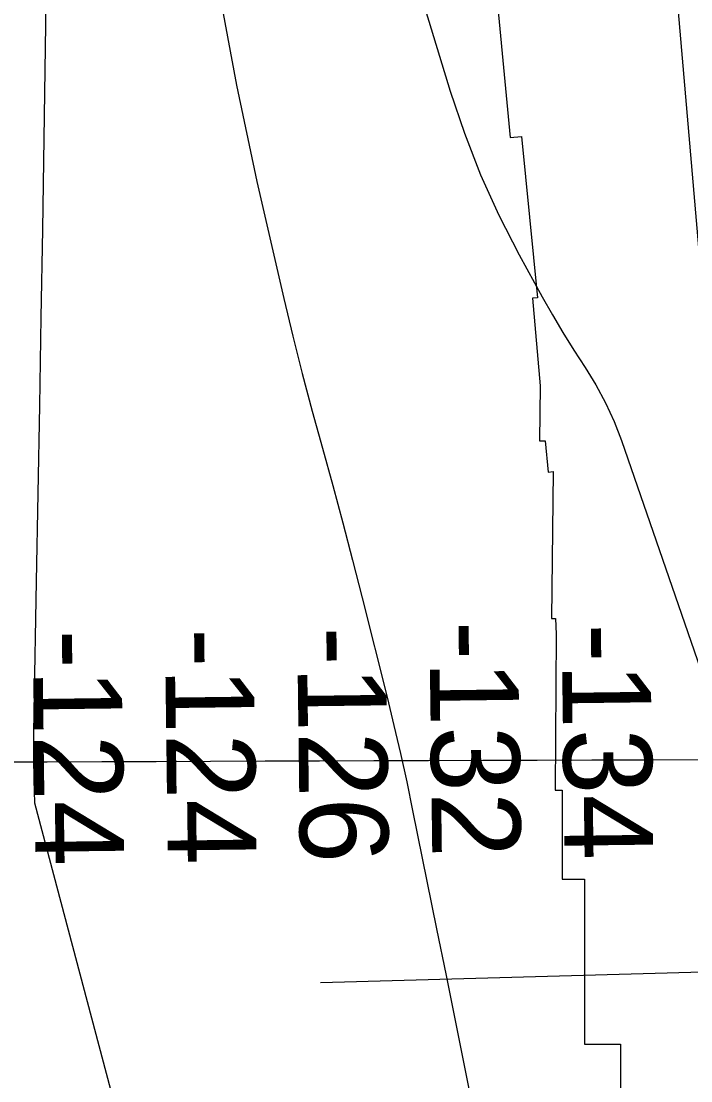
# Model space of a CAD drawing. Extents: x 3392644 to 3430565, y 576657 to 602123.
# Drawn here: x 3403450 to 3403956, y 587886 to 588688 of the extents above; entities that cross this region are included whole.
import ezdxf

# ---------------------------------------------------------------- set-up
doc = ezdxf.new("R2010")
doc.units = 0
for name, color, linetype in [('V-GRID-MAJR', 7, 'Continuous'), ('V-RIVR-RANG', 7, 'Continuous'), ('V-RRAP-RVMT', 7, 'Continuous'), ('V-TOPO-MINR', 7, 'Continuous')]:
    doc.layers.add(name, color=color, linetype=linetype)

msp = doc.modelspace()

# ---------------------------------------------------------------- linework, layer by layer
at = {"layer": 'V-GRID-MAJR'}
msp.add_spline([(3396759.069, 588105.428), (3402028.4020000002, 588122.6730000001), (3407297.732, 588140.684), (3412567.059, 588159.461), (3417836.383, 588179.004), (3423105.705, 588199.314), (3428375.023, 588220.3910000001), (3428375.024, 588220.3910000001)], degree=3, dxfattribs=at)
at = {"layer": 'V-RIVR-RANG'}
msp.add_line((3404773.4663000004, 587991.0334000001), (3403675.9011, 587960.1355), dxfattribs=at)
at = {"layer": 'V-RRAP-RVMT'}
for points in [[(3403787.4530000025, 589022.2620000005), (3403792.3760000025, 589022.6790000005), (3403803.1870000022, 588898.2240000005), (3403786.2820000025, 588896.8130000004), (3403799.6490000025, 588740.1650000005), (3403806.0080000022, 588740.6860000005), (3403819.3080000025, 588600.0000000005), (3403827.8170000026, 588600.7850000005), (3403839.9560000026, 588478.6580000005), (3403836.0480000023, 588478.3570000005), (3403842.0491820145, 588412.0041847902), (3403841.4620000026, 588370.4790000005), (3403845.8110243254, 588370.4109071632), (3403847.9510000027, 588346.7500000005), (3403851.9030192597, 588347.1069682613), (3403850.5170000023, 588235.8150000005), (3403853.604133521, 588235.7810275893), (3403853.9803775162, 588224.0148182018), (3403853.1720000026, 588106.0890000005), (3403858.7071260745, 588106.0502651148)], [(3403858.7071260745, 588106.0502651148), (3403858.6710000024, 588038.6260000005), (3403875.4310000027, 588038.7480000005), (3403875.4320000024, 587913.7160000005), (3403902.6370000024, 587913.8380000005), (3403902.6360000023, 587788.5640000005), (3403925.4690000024, 587788.5640000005), (3403925.6480000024, 587663.8410000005), (3403936.9150000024, 587663.8410000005), (3403936.9150000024, 587553.5380000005), (3403933.8540000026, 587553.5530000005), (3403934.0280000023, 587419.9890000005), (3403928.1980000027, 587310.5260000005), (3403951.0640000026, 587309.3500000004), (3403939.2910000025, 587215.2060000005), (3403940.488000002, 587215.0110000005), (3403924.5650000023, 587124.4060000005), (3403913.7950000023, 587126.3670000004), (3403888.8500000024, 586987.2380000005), (3403908.5240000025, 586983.7120000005), (3403886.9060000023, 586860.7560000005), (3403914.2310000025, 586855.8930000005), (3403892.6140000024, 586732.4500000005), (3403953.283649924, 586721.7793966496)]]:
    msp.add_lwpolyline(points, dxfattribs=at)
at = {"layer": 'V-TOPO-MINR'}
for points in [[(3403991.97834602, 588168.6326957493), (3403917.8935257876, 589028.6387163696)], [(3403471.7196410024, 588943.6111753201), (3403465.5392929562, 588530.2716853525), (3403464.497701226, 588463.7009697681), (3403463.3945110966, 588397.131317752), (3403462.198923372, 588330.5632610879), (3403460.9417372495, 588263.9962679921), (3403459.011862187, 588165.4341178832), (3403458.8154588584, 588148.1501057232), (3403458.808329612, 588130.8675702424), (3403459.0851114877, 588113.5872497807), (3403459.551167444, 588096.3084059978), (3403625.365806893, 587470.1941208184)], [(3403732.4809343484, 588770.8624191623), (3403773.8831140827, 588635.0073053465), (3403784.6929227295, 588603.1021186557), (3403796.775585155, 588571.7328043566), (3403810.767528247, 588541.1672986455), (3403826.0323251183, 588511.1376653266), (3403843.4885971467, 588479.2709980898), (3403851.1665183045, 588465.6883321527), (3403859.081644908, 588452.249673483), (3403867.3525796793, 588439.0270257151), (3403875.860719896, 588425.9483852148), (3403884.0042079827, 588412.7079417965), (3403891.4337994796, 588399.1124415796), (3403897.7925460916, 588384.9843561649), (3403903.437396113, 588370.5012139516), (3403979.915626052, 588149.3539946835)], [(3403598.661832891, 588712.8074390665), (3403612.2857686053, 588639.5211201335), (3403627.7353002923, 588566.5391246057), (3403648.193729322, 588478.0649569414), (3403654.992424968, 588449.6015972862), (3403662.0640281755, 588421.2083047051), (3403669.5449927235, 588392.9201127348), (3403677.298864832, 588364.7019878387), (3403685.126776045, 588336.5016614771), (3403692.780401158, 588308.2549747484), (3403700.1725971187, 588279.9387474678), (3403707.3905069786, 588251.5761598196), (3403726.17193478, 588176.3214248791), (3403731.343032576, 588154.9891738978), (3403736.3213192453, 588133.6133892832), (3403741.0103892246, 588112.1723042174), (3403745.506648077, 588090.6876855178), (3403763.6432930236, 588001.007506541), (3403770.7772274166, 587965.7180530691), (3403777.9074511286, 587930.4278501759), (3403785.032108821, 587895.1365231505), (3403792.1530558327, 587859.8444467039)]]:
    msp.add_lwpolyline(points, dxfattribs=at)

# ---------------------------------------------------------------- texts
at = {"layer": 'V-RIVR-RANG'}
for s, p in [('-132', (3403758.1183520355, 588233.8326360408)), ('-134', (3403858.1503098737, 588231.9582966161)), ('-124', (3403458.178029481, 588227.3247803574)), ('-124', (3403558.173029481, 588228.3507803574)), ('-126', (3403658.164669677, 588229.6415384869))]:
    msp.add_text(s, height=67.00000000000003, rotation=270.7298055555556, dxfattribs=at).set_placement(p)

doc.saveas('drawing.dxf')
